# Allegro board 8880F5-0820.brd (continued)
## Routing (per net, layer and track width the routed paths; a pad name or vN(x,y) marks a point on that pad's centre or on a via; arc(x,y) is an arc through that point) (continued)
N26504452: length 3
  BOTTOM w0.119: UNK4K30.3 310.01,154.17 309.53,154.64 UNK4R63.2
N26504453: length 3
  BOTTOM w0.119: UNK4K30.4 312.21,154.17 312.68,154.64 UNK4R64.1
N26504454: length 3
  BOTTOM w0.119: UNK4R101.1 312.68,142.03 312.21,142.5 UNK4K30.5
N26504455: length 3
  BOTTOM w0.119: UNK4R100.2 309.53,142.03 310.01,142.5 UNK4K30.6
N26504536: length 3
  BOTTOM w0.119: UNK4R67.2 393.35,173.95 393.83,173.48 UNK4K16.3
N26504537: length 3
  BOTTOM w0.119: UNK4R68.1 396.5,173.95 396.03,173.48 UNK4K16.4
N26504538: length 3
  BOTTOM w0.119: UNK4R70.1 396.5,161.33 396.03,161.8 UNK4K16.5
N26504539: length 3
  BOTTOM w0.119: UNK4R69.2 393.35,161.33 393.83,161.8 UNK4K16.6
N26504561: length 3
  BOTTOM w0.119: UNK4R30.1 396.5,144.57 396.03,145.04 UNK4K6.5
N26504563: length 3
  BOTTOM w0.119: UNK4R27.2 393.35,157.18 393.83,156.71 UNK4K6.3
N26504564: length 3
  BOTTOM w0.119: UNK4R28.1 396.5,157.18 396.03,156.71 UNK4K6.4
N26504565: length 3
  BOTTOM w0.119: UNK4K6.6 393.83,145.04 393.35,144.57 UNK4R29.2
N26504566: length 3
  BOTTOM w0.119: UNK4K7.5 413.77,181.32 413.3,180.84 UNK4R34.1
N26504568: length 3
  BOTTOM w0.119: UNK4K7.3 425.44,183.52 425.92,183.99 UNK4R31.2
N26504569: length 3
  BOTTOM w0.119: UNK4R32.1 425.92,180.84 425.44,181.32 UNK4K7.4
N26504570: length 3
  BOTTOM w0.119: UNK4K7.6 413.77,183.52 413.3,183.99 UNK4R33.2
N26504612: length 3
  BOTTOM w0.119: UNK4K11.3 380.62,189.99 380.15,190.46 UNK4R39.2
N26504613: length 3
  BOTTOM w0.119: UNK4R40.1 383.29,190.46 382.82,189.99 UNK4K11.4
N26504614: length 3
  BOTTOM w0.119: UNK4K8.5 405.17,130.05 405.64,129.58 UNK4R38.1
N26504616: length 3
  BOTTOM w0.119: UNK4K8.6 402.97,130.05 402.5,129.58 UNK4R37.2
N26504617: length 3
  BOTTOM w0.119: UNK4K11.6 380.62,178.31 380.15,177.84 UNK4R41.2
N26504618: length 3
  BOTTOM w0.119: UNK4K11.5 382.82,178.31 383.29,177.84 UNK4R42.1
N26504660: length 3
  BOTTOM w0.119: UNK4R26.1 423.68,144.57 423.2,145.04 UNK4K5.5
N26504662: length 3
  BOTTOM w0.119: UNK4K5.3 421,156.71 420.53,157.18 UNK4R23.2
N26504663: length 3
  BOTTOM w0.119: UNK4R24.1 423.68,157.18 423.2,156.71 UNK4K5.4
N26504664: length 3
  BOTTOM w0.119: UNK4K5.6 421,145.04 420.53,144.57 UNK4R25.2
N26504685: length 3
  BOTTOM w0.119: UNK4K3.5 325.92,129.8 326.39,129.33 UNK4R18.1
N26504686: length 3
  BOTTOM w0.119: UNK4R17.2 323.25,129.33 323.72,129.8 UNK4K3.6
N26504687: length 3
  BOTTOM w0.119: UNK4K3.4 325.92,141.47 326.39,141.94 UNK4R16.1
N26504688: length 3
  BOTTOM w0.119: UNK4K3.3 323.72,141.47 323.25,141.94 UNK4R15.2
N26504691: length 3
  BOTTOM w0.119: UNK4R10.1 423.17,161.33 422.7,161.8 UNK4K1.5
N26504692: length 3
  BOTTOM w0.119: UNK4R9.2 420.02,161.33 420.5,161.8 UNK4K1.6
N26504693: length 3
  BOTTOM w0.119: UNK4K1.4 422.7,173.48 423.17,173.95 UNK4R8.1
N26504694: length 3
  BOTTOM w0.119: UNK4K1.3 420.5,173.48 420.02,173.95 UNK4R7.2
N26504696: length 3
  BOTTOM w0.119: UNK4K2.3 407.54,156.71 407.07,157.18 UNK4R11.2
N26504697: length 3
  BOTTOM w0.119: UNK4K2.4 409.74,156.71 410.21,157.18 UNK4R12.1
N26504698: length 3
  BOTTOM w0.119: UNK4R22.1 411.48,207.31 411.01,207.78 UNK4K4.5
N26504700: length 3
  BOTTOM w0.119: UNK4K4.3 408.81,219.45 408.34,219.92 UNK4R19.2
N26504701: length 3
  BOTTOM w0.119: UNK4R20.1 411.48,219.92 411.01,219.45 UNK4K4.4
N26504702: length 3
  BOTTOM w0.119: UNK4R21.2 408.34,207.31 408.81,207.78 UNK4K4.6
N26504703: length 3
  BOTTOM w0.119: UNK4K2.5 409.74,145.04 410.21,144.57 UNK4R14.1
N26504704: length 3
  BOTTOM w0.119: UNK4R13.2 407.07,144.57 407.54,145.04 UNK4K2.6
N26504896:
  vias: v1(456.25,190.45)
N26504897:
  vias: v1(451.68,190.45)
N26504937:
  vias: v1(451.62,188.98)
N26504938:
  vias: v1(451.62,181.36)
N26504999:
  vias: v1(483.1,190.25)
N26505003:
  vias: v1(483.1,197.87)
N26509126:
  vias: v1(491.1,183.24)
N26509130:
  vias: v1(490.86,169.47)
N26509132:
  vias: v1(485.8,169.47)
N26509139:
  vias: v1(477.53,175.15)
N26509173:
  vias: v1(477.43,161.55)
N26509211:
  vias: v1(485.8,183.19)

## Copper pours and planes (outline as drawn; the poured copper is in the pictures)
Net_1 on L02_DGND: 8.32,299.68 8.32,129.45 568.71,129.45 568.71,299.68
Net_2 on L02_DGND: 230.83,204.63 230.83,164.63 270.83,164.63 270.83,204.63
Net_2 on L02_DGND: 310.83,204.63 310.83,164.63 350.83,164.63 350.83,204.63
Net_2 on L02_DGND: 230.83,264.63 230.83,224.63 270.83,224.63 270.83,264.63
Net_2 on L02_DGND: 310.83,264.63 310.83,224.63 350.83,224.63 350.83,264.63

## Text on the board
User.Comments: CR_SS_6 | CR_2_2 | CR_RELAY_19 | CR_4_2 | CR_3_1 | CR_2_3 | CR_UNNAMED_2 | CR_UNNAMED_3 | CR_QQ_28 | CR_A_23 | CR_5_1 | CR_5_2 | CR_QQ_12 | CR_QQ_11 | CR_A_28 | CR_A_21 | CR_A_25 | CR_A_26 | CR_A_30 | CR_A_32 | CR_A_22 | CR_A_24 | CR_A_27 | CR_A_29 | CR_A_31 | CR_A_20
